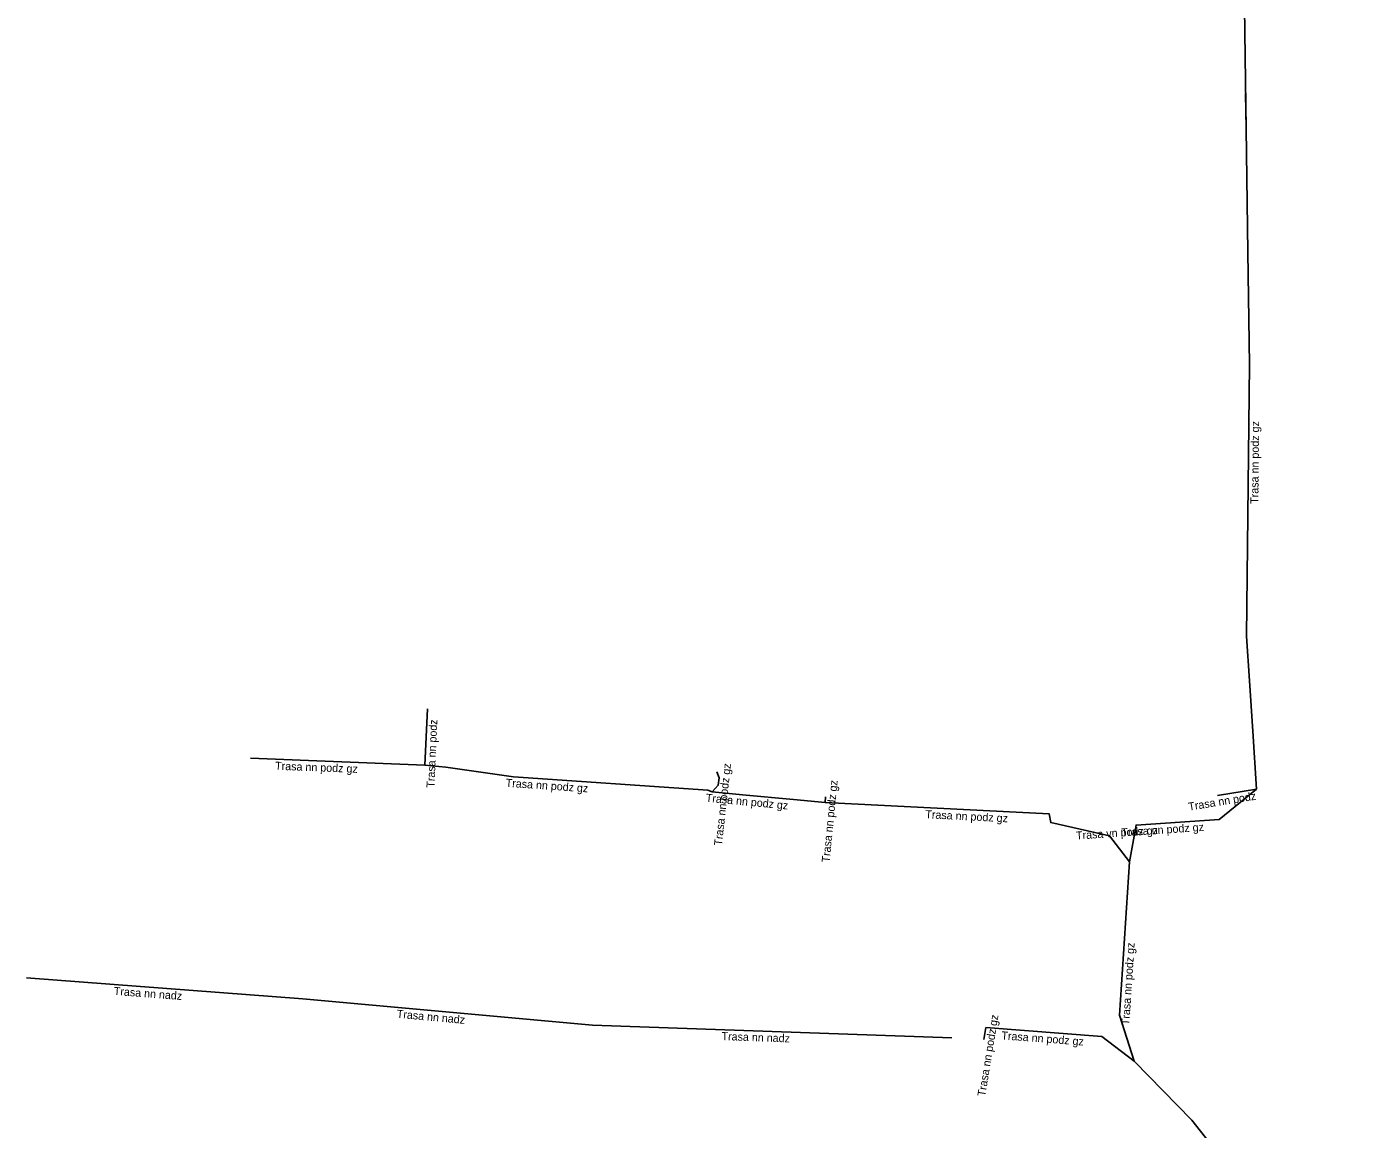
# Model space of a CAD drawing. Extents: x -778200 to -777730, y -1024936 to -1024518.
# Drawn here: x -778008.8 to -777925.8, y -1024730.5 to -1024661.6 of the extents above; entities that cross this region are included whole.
import ezdxf

# ---------------------------------------------------------------- set-up
doc = ezdxf.new("R2010")
doc.units = 0
for name, color, linetype in [('Popiskový text - Ostatní atributy Trasy', 7, 'Continuous'), ('Spojnice NN', 7, 'Continuous'), ('Spojnice VN', 7, 'Continuous')]:
    doc.layers.add(name, color=color, linetype=linetype)

msp = doc.modelspace()

# ---------------------------------------------------------------- linework, layer by layer
at = {"layer": 'Spojnice NN'}
for points in [[(-777931.943, -1024709.204), (-777932.182, -1024705.593), (-777932.391, -1024702.446), (-777932.575, -1024699.644), (-777932.398, -1024682.678), (-777932.491, -1024675.664), (-777932.595, -1024667.946), (-777932.649, -1024665.746)], [(-777983.899, -1024707.706), (-777983.746, -1024704.2)], [(-777994.808, -1024707.28), (-777983.899, -1024707.706)], [(-777983.899, -1024707.706), (-777982.592, -1024707.835), (-777978.376, -1024708.436), (-777966.226, -1024709.278), (-777965.96, -1024709.374)], [(-777965.96, -1024709.374), (-777965.582, -1024708.967), (-777965.53, -1024708.499), (-777965.659, -1024708.128)], [(-777965.96, -1024709.374), (-777964.052, -1024709.557), (-777960.885, -1024709.861), (-777958.907, -1024710.051)], [(-777958.907, -1024710.051), (-777958.871, -1024709.687)], [(-777939.88, -1024713.74), (-777939.476, -1024711.454), (-777934.291, -1024711.098), (-777931.943, -1024709.204)], [(-777931.943, -1024709.204), (-777934.389, -1024709.605)], [(-777958.907, -1024710.051), (-777944.903, -1024710.76), (-777944.803, -1024711.297), (-777941.134, -1024712.114), (-777939.88, -1024713.74)], [(-777939.603, -1024726.2), (-777940.511, -1024723.334), (-777939.88, -1024713.74)], [(-777991.537, -1024722.302), (-778008.787, -1024720.996)], [(-777973.427, -1024723.946), (-777991.537, -1024722.302)], [(-777950.99, -1024724.74), (-777973.427, -1024723.946)], [(-777948.854, -1024724.108), (-777948.976, -1024724.856)], [(-777939.603, -1024726.2), (-777941.624, -1024724.66), (-777948.854, -1024724.108)], [(-777926.024, -1024758.713), (-777925.859, -1024756.323), (-777925.772, -1024750.894), (-777925.919, -1024743.043), (-777926.069, -1024738.968), (-777927.663, -1024737.846), (-777932.279, -1024734.598), (-777936.001, -1024729.893), (-777939.603, -1024726.2)]]:
    msp.add_lwpolyline(points, dxfattribs=at)
at = {"layer": 'Spojnice VN'}
msp.add_lwpolyline([(-777932.279, -1024734.598), (-777936.001, -1024729.893), (-777939.603, -1024726.2), (-777940.511, -1024723.334), (-777939.88, -1024713.74), (-777939.476, -1024711.454), (-777934.291, -1024711.098), (-777931.943, -1024709.204), (-777932.182, -1024705.593), (-777932.391, -1024702.446), (-777932.575, -1024699.644), (-777932.398, -1024682.678), (-777932.491, -1024675.664), (-777932.595, -1024667.946), (-777932.636, -1024664.966), (-777932.685, -1024661.924), (-777932.868, -1024647.938)], dxfattribs=at)

# ---------------------------------------------------------------- texts
at = {"layer": 'Popiskový text - Ostatní atributy Trasy'}
for s, rotation, p in [('Trasa nn podz gz', 89.40228, (-777931.839, -1024691.385)), ('Trasa nn podz', 87.50123, (-777983.31, -1024709.126)), ('Trasa nn podz gz', 357.76372, (-777993.269, -1024707.991)), ('Trasa nn podz gz', 83.65981, (-777965.349, -1024712.755)), ('Trasa nn podz gz', 356.03329, (-777978.869, -1024709.053)), ('Trasa nn podz gz', 84.35175, (-777958.625, -1024713.807)), ('Trasa nn podz gz', 354.51698, (-777966.372, -1024709.988)), ('Trasa nn podz', 9.31031, (-777936.167, -1024710.555)), ('Trasa nn podz gz', 357.10168, (-777952.651, -1024711.019)), ('Trasa nn podz gz', 3.92774, (-777940.376, -1024712.167)), ('Trasa vn podz gz', 3.92774, (-777943.209, -1024712.362)), ('Trasa nn podz gz', 86.23706, (-777939.901, -1024723.965)), ('Trasa nn nadz', 355.67039, (-778003.35, -1024722.06)), ('Trasa nn nadz', 354.81299, (-777985.675, -1024723.486)), ('Trasa nn podz gz', 80.73653, (-777948.9, -1024728.429)), ('Trasa nn nadz', 357.97326, (-777965.378, -1024724.882)), ('Trasa nn podz gz', 355.63402, (-777947.904, -1024724.833))]:
    msp.add_text(s, height=0.5, rotation=rotation, dxfattribs=at).set_placement(p)

doc.saveas('drawing.dxf')
